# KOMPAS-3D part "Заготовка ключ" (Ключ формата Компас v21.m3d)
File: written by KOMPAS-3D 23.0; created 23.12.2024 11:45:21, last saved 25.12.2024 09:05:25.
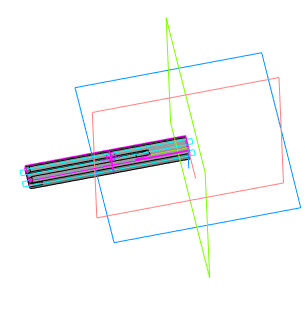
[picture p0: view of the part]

Document properties: Автор: admin; Полное имя файла: D:\Информация пользователя\Desktop\Арена 2000\Ключ\Ключ формата Компас v21.m3d

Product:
- Part/product: Заготовка ключ
    Масса: 0.005622

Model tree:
1. Операция без истории:1
2. Эскиз:1
3. Эскиз:2  (with: Операция без истории:1)
4. Эскиз:3
5. Смещенная плоскость:1
     Расстояние = 1
6. Эскиз:5
7. Эскиз:6  (with: Элемент выдавливания:1)
8. Смещенная плоскость:2  (with: Элемент выдавливания:1)
     Расстояние = -1
9. Эскиз:7
10. Эскиз:8
11. Эскиз:9
12. Эскиз:10  (with: Операция без истории:1)
13. Эскиз:11  (with: Операция без истории:1)
14. Эскиз:12  (with: Операция без истории:1)
15. Средняя плоскость:5  (with: Операция без истории:1)

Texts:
  Точка начала. Х
  Точка начала. Y
  Точка начала. Z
